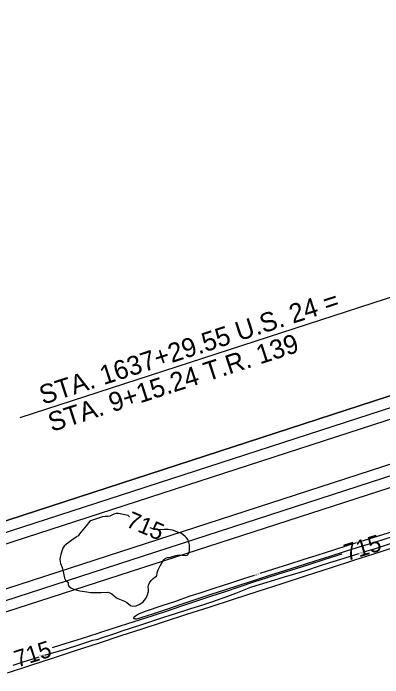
# Model space of a CAD drawing. Extents: x -468556195 to 3353078, y -306091294 to 1252632.
# Drawn here: x 1828648 to 1829375, y 533219 to 534528 of the extents above; entities that cross this region are included whole.
import ezdxf

# ---------------------------------------------------------------- set-up
doc = ezdxf.new("R2010")
doc.units = 0
for name, color, linetype in [('Default', 7, 'Continuous'), ('DT_X_Contour_Minor', 7, 'Continuous'), ('Level 14', 7, 'Continuous'), ('Level 19', 7, 'Continuous'), ('Level 40', 7, 'Continuous'), ('SC_Shading3', 7, 'Continuous')]:
    doc.layers.add(name, color=color, linetype=linetype)

msp = doc.modelspace()

# ---------------------------------------------------------------- linework, layer by layer
at = {"layer": 'Default'}
for points in [[(1827117.1, 533034.5), (1827123.3, 533015.5), (1834732.4, 535485.8), (1834724, 535511.6)], [(1827162.8, 532893.7), (1827168.8, 532875.3), (1833162.6, 534815.3), (1833154.9, 534839.7)]]:
    msp.add_lwpolyline(points, close=True, dxfattribs=at)
at = {"layer": 'DT_X_Contour_Minor'}
for points in [[(1829340.4, 533467.6), (1829359, 533473.4), (1829386.6, 533482.1), (1829419.1, 533492.2), (1829446.6, 533500.7), (1829466, 533507.2), (1829479.5, 533512), (1829494.1, 533516.6), (1829523, 533525.6), (1829552.3, 533535.6), (1829581.9, 533546), (1829596.5, 533550.8), (1829626, 533559.8), (1829637.1, 533563.5)], [(1828877, 533536.4), (1828874.4, 533538.6), (1828871.5, 533539.7), (1828855.2, 533542.7), (1828850.7, 533542.7), (1828846.5, 533541.4), (1828842.6, 533539.4), (1828838.5, 533537.8), (1828834.2, 533537.1), (1828829.3, 533536.8), (1828823.9, 533536.1), (1828817.8, 533534.5), (1828800.3, 533528.4), (1828799.3, 533527.4), (1828791.7, 533518.2), (1828778.5, 533502.4), (1828776.8, 533499.6), (1828776.4, 533498.5), (1828775.5, 533498), (1828773.6, 533497.3), (1828771.8, 533496.2), (1828763.6, 533490.5), (1828753.2, 533482.6), (1828748.8, 533478.3), (1828746.2, 533474.3), (1828744.6, 533470.3), (1828742.1, 533462.1), (1828740.9, 533456.8), (1828740.2, 533451.9), (1828740.4, 533448), (1828741.4, 533444.6), (1828744.3, 533436.2), (1828747.1, 533425.3), (1828749.4, 533415.1), (1828751, 533411.6), (1828753, 533409.5), (1828755, 533408.3), (1828756.1, 533407.1), (1828756.1, 533402.7), (1828757.6, 533399.7), (1828761.6, 533396.5), (1828767.5, 533393.6), (1828773.8, 533391.5), (1828779.6, 533390.3), (1828793, 533388.8), (1828800, 533386.9), (1828821.1, 533387), (1828834.2, 533387.6), (1828838.5, 533386.6), (1828842.5, 533384.3), (1828851.3, 533376.7), (1828853.8, 533375.4), (1828867.1, 533370.4), (1828871.9, 533367.7), (1828879.1, 533361.7), (1828883.7, 533360.3), (1828890, 533361), (1828897.3, 533363.9), (1828904.1, 533368.8), (1828909.4, 533375.4), (1828912.7, 533382.5), (1828914.3, 533389), (1828914.3, 533393.8), (1828913.8, 533397.7), (1828914.3, 533401.6), (1828916.5, 533406.3), (1828920, 533411.1), (1828923.7, 533415), (1828926.8, 533417.2), (1828930.3, 533419.5), (1828930.9, 533421), (1828931.5, 533425.5), (1828932.2, 533428.4), (1828933.5, 533431.7), (1828937.7, 533439.9), (1828942.9, 533448.6), (1828945.4, 533451.9), (1828947.6, 533454.2), (1828949.7, 533455.5), (1828951.7, 533456), (1828954.1, 533456.2), (1828957.6, 533456.9), (1828968.4, 533460.3), (1828974.8, 533461.3), (1828981, 533460.9), (1828986.5, 533460.2), (1828990.9, 533460.9), (1828993.6, 533464), (1828995, 533469), (1828995.4, 533474.9), (1828995, 533481), (1828993.9, 533486.5), (1828992, 533491.3), (1828989.4, 533494.8), (1828986.5, 533497.5), (1828979.1, 533503.6), (1828975.9, 533504.6)], [(1828975.9, 533504.6), (1828973.4, 533505.4), (1828961.5, 533509.9), (1828957.4, 533510.8), (1828953.5, 533511.2), (1828945.1, 533511.2), (1828932.3, 533510.9), (1828928.1, 533511.3), (1828923.3, 533512.5), (1828917.8, 533514.6)], [(1829394, 533506.9), (1829366.8, 533498.2), (1829337.3, 533489), (1829334.9, 533488.3)], [(1829122.2, 533420.7), (1829101.3, 533413.9), (1829075.6, 533405.7), (1829042.8, 533395), (1829013.5, 533385.5), (1828996, 533379.7), (1828967.3, 533369.7), (1828940.9, 533360.9), (1828907.9, 533350), (1828902.6, 533347.9), (1828894.7, 533344.2), (1828888.8, 533340.8), (1828886.3, 533338.6), (1828885, 533337.1), (1828884.9, 533336.5), (1828885.3, 533336.1), (1828887.3, 533335.7), (1828888.7, 533335.5), (1828890.8, 533335.6), (1828894.1, 533336.2), (1828904.1, 533339), (1828920.8, 533344.4), (1828952.4, 533355), (1828978.7, 533363.9), (1829010.3, 533374.8), (1829038, 533383.8), (1829064.4, 533392.4), (1829095.2, 533402.3), (1829122.1, 533411.1), (1829155, 533421.8), (1829182.7, 533430.5), (1829209.7, 533439), (1829242.6, 533449.4), (1829270.3, 533458.3), (1829303.9, 533469.1), (1829333.4, 533478.1), (1829361.6, 533486.8), (1829394.7, 533497.3)], [(1829323.5, 533484.7), (1829307, 533479.7), (1829278.3, 533470.5), (1829245.6, 533460), (1829218.3, 533451.4), (1829190.2, 533442.6), (1829160.7, 533433.2), (1829133.7, 533424.4)], [(1828710.7, 533263.7), (1828721.5, 533266.9), (1828753.1, 533276.3), (1828775.3, 533283.5), (1828805.1, 533293.1), (1828812.2, 533294.9), (1828815.2, 533295.6), (1828820.1, 533297), (1828846.2, 533306.1), (1828864.6, 533312.2), (1828895.4, 533322.2), (1828915.1, 533328.6), (1828944.9, 533338.3), (1828969.8, 533346.2), (1828996, 533354.7), (1829023.2, 533363.6), (1829040.8, 533369.6), (1829070.3, 533380.2), (1829086.3, 533386), (1829116, 533397.5), (1829126.5, 533401.2), (1829154.8, 533409.7), (1829182.2, 533417.9), (1829213.4, 533427.2), (1829224.2, 533430.5), (1829251.2, 533439.7), (1829271.4, 533446.5), (1829299.3, 533454.9), (1829326.4, 533463.2), (1829329, 533464)], [(1828725.5, 533278.9), (1828752.5, 533287.3), (1828782.6, 533296.9), (1828815.2, 533307.1), (1828820.9, 533308.8), (1828841.2, 533315.4), (1828874, 533326), (1828896.9, 533333.3), (1828923.9, 533341.9), (1828952.2, 533351.3), (1828980.2, 533360.7), (1829011.4, 533371.3), (1829037.1, 533379.7), (1829065.9, 533389.3), (1829093, 533398.3), (1829122, 533408.3), (1829148.6, 533416.8), (1829171.1, 533423.8), (1829203.4, 533433.8), (1829230.2, 533442.2), (1829260.1, 533452), (1829289.1, 533461.3), (1829295.6, 533463.3)], [(1828648.2, 533244.4), (1828669.9, 533251.3), (1828693.1, 533258.3), (1828699.3, 533260.2)]]:
    msp.add_lwpolyline(points, dxfattribs=at)
at = {"layer": 'Level 14'}
msp.add_lwpolyline([(1829417.1, 533482.1), (1829369.9, 533466.9), (1829320.2, 533450.9), (1829271.9, 533435.2), (1829224.6, 533419.8), (1829176.8, 533404.3), (1829127.5, 533388.3), (1829080.9, 533373.4), (1829033.4, 533357.9), (1828989.4, 533343.6), (1828945.2, 533329.2), (1828901.4, 533314.9), (1828860.2, 533301.6), (1828815.6, 533286.8), (1828770.1, 533272.2), (1828725.1, 533257.5), (1828680.5, 533242.9), (1828636.2, 533228.6)], dxfattribs=at)
at = {"layer": 'Level 40'}
msp.add_line((1828661.9, 533731.8), (1829449.6, 533987.6), dxfattribs=at)
at = {"layer": 'SC_Shading3'}
for points in [[(1827130.1, 532994.6), (1827117.1, 533034.5), (1834724, 535511.6), (1834739.2, 535464.9)], [(1827156, 532914.7), (1827168.8, 532875.3), (1833162.6, 534815.3), (1833148.1, 534860)]]:
    msp.add_lwpolyline(points, close=True, dxfattribs=at)

# ---------------------------------------------------------------- texts
at = {"layer": 'Level 19'}
for s, height, rotation, p in [('715', 33, 337.0825, (1828868.3, 533517.6)), ('715', 33, 17.0856, (1829305.2, 533449)), ('714', 4, 17.0226, (1829324.8, 533483.1)), ('718', 4, 17.4236, (1829330.3, 533462.3)), ('714', 4, 17.9508, (1829123.6, 533419.1)), ('715', 33, 17.8247, (1828656.4, 533239.4)), ('718', 4, 16.8564, (1828700.6, 533258.5))]:
    msp.add_text(s, height=height, rotation=rotation, dxfattribs=at).set_placement(p)
at = {"layer": 'Level 40'}
for s, p in [('STA. 1637+29.55 U.S. 24 =', (1828706.8, 533756.7)), ('STA. 9+15.24 T.R. 139', (1828724.2, 533703.2))]:
    msp.add_text(s, height=37.5, rotation=17.9864, dxfattribs=at).set_placement(p)

doc.saveas('drawing.dxf')
